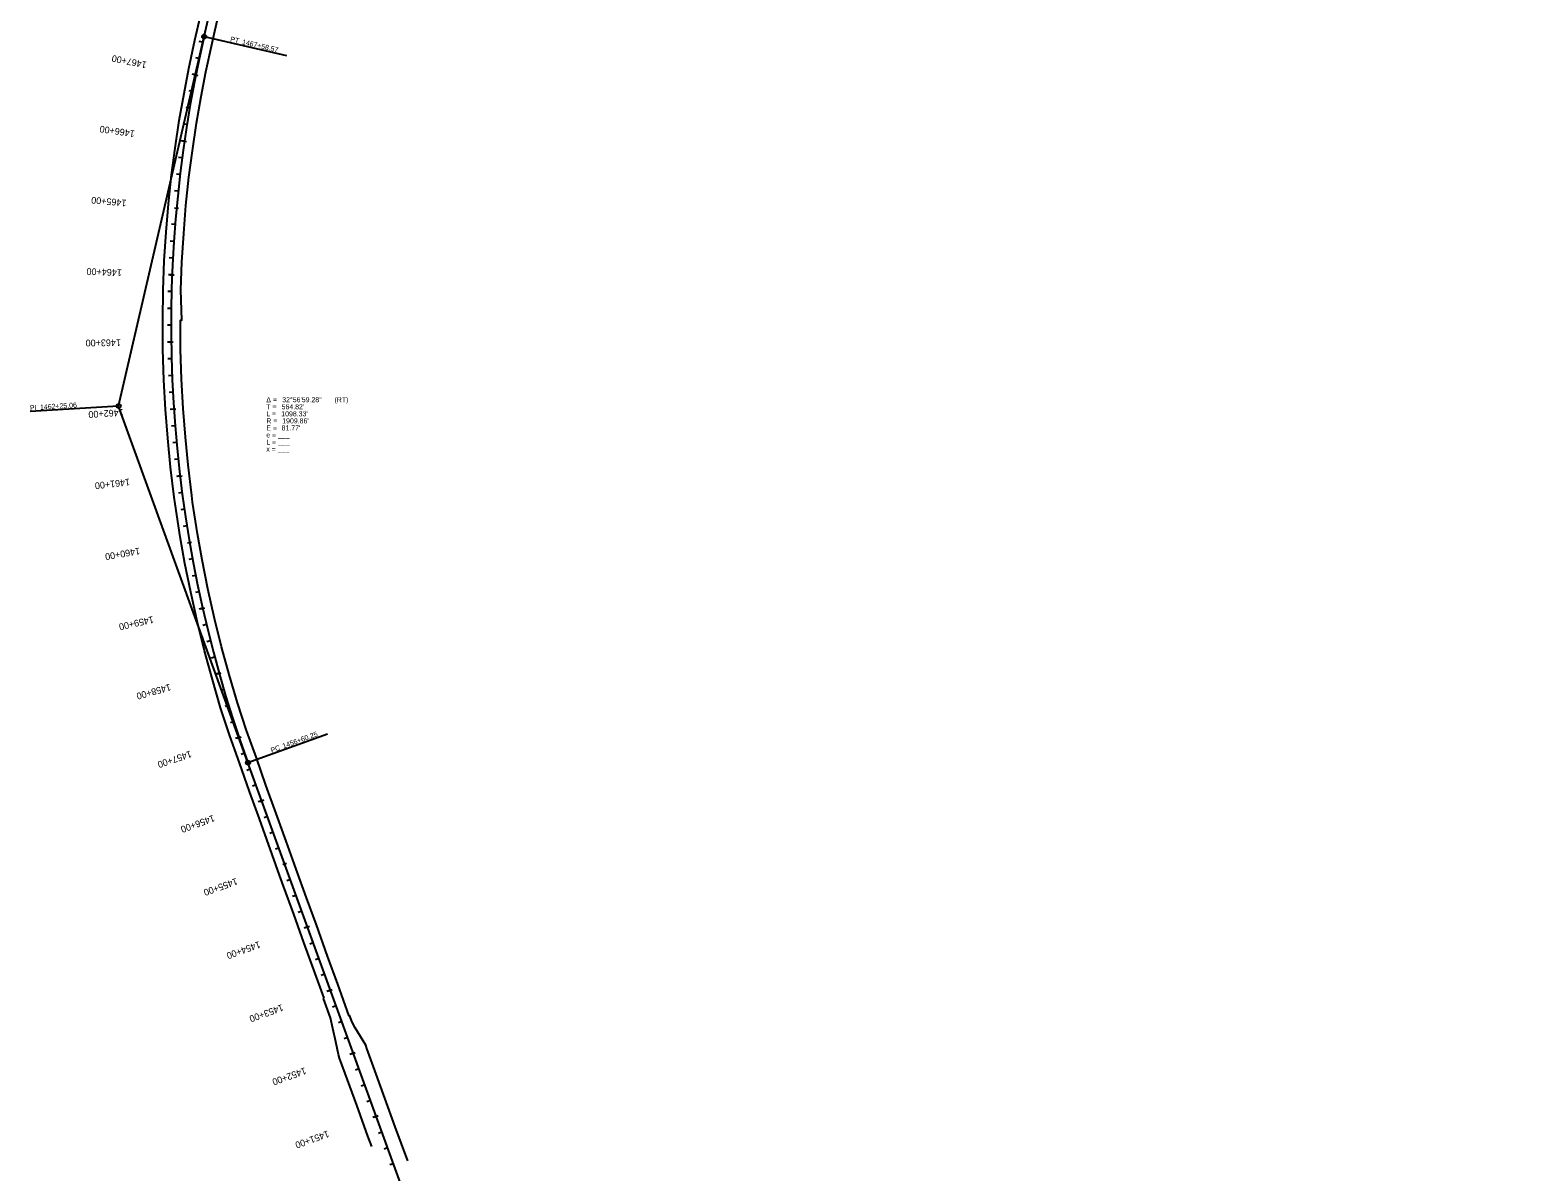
# Model space of a CAD drawing. Extents: x 21596470 to 21601942, y 8263806 to 8275912.
# Drawn here: x 21596470 to 21598714, y 8265512 to 8267212 of the extents above; entities that cross this region are included whole.
import ezdxf

# ---------------------------------------------------------------- set-up
doc = ezdxf.new("R2010")
doc.units = 0
for name, color, linetype in [('DsnShtInsideBorder', 7, 'Continuous'), ('Level 1', 7, 'Continuous'), ('Level 20', 7, 'Continuous'), ('SurTxtLeaderLine', 7, 'Continuous'), ('SurTxtSurveyInformation', 7, 'Continuous'), ('wetNoteSoil', 7, 'Continuous')]:
    doc.layers.add(name, color=color, linetype=linetype)

msp = doc.modelspace()

# ---------------------------------------------------------------- linework, layer by layer
at = {"layer": 'DsnShtInsideBorder'}
for p, q in [((21596728.7, 8267202.6), (21596851.5, 8267174.2)), ((21596851.5, 8267174.2), (21596851.5, 8267174.2)), ((21596601.4, 8266652.3), (21596469.7, 8266644.3)), ((21596469.7, 8266644.3), (21596469.7, 8266644.3)), ((21596793.9, 8266121.3), (21596912.3, 8266164.2)), ((21596912.3, 8266164.2), (21596912.3, 8266164.2))]:
    msp.add_line(p, q, dxfattribs=at)
for centre in [(21596728.7, 8267202.6), (21596601.4, 8266652.3), (21596793.9, 8266121.3)]:
    msp.add_circle(centre, 3.12, dxfattribs=at)
at = {"layer": 'Level 1'}
for p, q in [((21596716.4, 8267145.3), (21596711, 8267146.4)), ((21596699.4, 8267046.8), (21596694, 8267047.5)), ((21596684.6, 8266947.7), (21596690.7, 8266947.2)), ((21596681.1, 8266847.7), (21596675.6, 8266847.9)), ((21596679.7, 8266747.7), (21596674.3, 8266747.6)), ((21596683.6, 8266647.8), (21596678.2, 8266647.4)), ((21596692.7, 8266548.2), (21596687.3, 8266547.6)), ((21596704, 8266448.8), (21596710.1, 8266449.8)), ((21596726.5, 8266351.2), (21596721.2, 8266350)), ((21596751.1, 8266254.3), (21596745.9, 8266252.8)), ((21596780.7, 8266158.8), (21596775.6, 8266157)), ((21596814.4, 8266064.6), (21596809.3, 8266062.8)), ((21596845.6, 8265969.6), (21596851.4, 8265971.7)), ((21596882.6, 8265876.6), (21596877.4, 8265874.7)), ((21596916.6, 8265782.6), (21596911.5, 8265780.7)), ((21596950.7, 8265688.6), (21596945.6, 8265686.7)), ((21596984.8, 8265594.6), (21596979.7, 8265592.7))]:
    msp.add_line(p, q, dxfattribs=at)
at = {"layer": 'Level 20'}
for p, q in [((21596601.4, 8266652.3), (21598714.2, 8275785)), ((21596728.7, 8267202.6), (21598588.8, 8275242.6)), ((21597632.1, 8263808.8), (21596601.4, 8266652.3)), ((21597632.1, 8263808.8), (21596793.9, 8266121.3))]:
    msp.add_line(p, q, dxfattribs=at)
msp.add_arc((21598589.4, 8266772.1), 1909.9, 166.974, 199.9238, dxfattribs=at)
msp.add_arc((21598589.4, 8266772.1), 1909.9, 166.974, 199.9238, dxfattribs=at)
at = {"layer": 'SurTxtLeaderLine'}
for points in [[(21596944.8, 8265743.6), (21596927.5, 8265791.2), (21596912.5, 8265833.3), (21596895.8, 8265879.9), (21596881.2, 8265919.8), (21596865.6, 8265962.8), (21596850.8, 8266004.4), (21596836, 8266045.3), (21596820.7, 8266087.5), (21596806.4, 8266128.4), (21596791.9, 8266169.3), (21596778.2, 8266210.3), (21596765.7, 8266252.3), (21596754.6, 8266293.9), (21596744.2, 8266335.7), (21596734.3, 8266380.1), (21596725.6, 8266423.2), (21596718.8, 8266462.2), (21596711.5, 8266509), (21596710.4, 8266519.1), (21596704.8, 8266564.8), (21596700.9, 8266606.2), (21596697.3, 8266648.6), (21596694.9, 8266692.2), (21596693.7, 8266736.6), (21596693.3, 8266780), (21596695.4, 8266780), (21596694, 8266825.2), (21596695.4, 8266866.8), (21596698.2, 8266909.4), (21596701.5, 8266951.2), (21596705.9, 8266993), (21596711.3, 8267032.5), (21596717.4, 8267073.6), (21596724.2, 8267113.2), (21596731.4, 8267150.2), (21596740.4, 8267192.7), (21596750.3, 8267234.8)], [(21597031.7, 8265528.4), (21597013.3, 8265579), (21596997.9, 8265621.4), (21596983, 8265662.7), (21596971.1, 8265695.8), (21596969.2, 8265700.6), (21596953.4, 8265726.5), (21596948.6, 8265735.7), (21596945.6, 8265744), (21596944.8, 8265743.6)]]:
    msp.add_lwpolyline(points, dxfattribs=at)
at = {"layer": 'SurTxtSurveyInformation'}
for points in [[(21596907.2, 8265770.4), (21596892.1, 8265812.6), (21596877.2, 8265853.6), (21596862.2, 8265895.5), (21596847, 8265937.5), (21596841, 8265953.8), (21596810.9, 8266037.4), (21596796, 8266078.5), (21596781.1, 8266120.8), (21596766.8, 8266161.2), (21596753, 8266202.8), (21596741, 8266245), (21596729, 8266287.8), (21596718.8, 8266329.9), (21596708.7, 8266375.1), (21596700, 8266418), (21596693, 8266457.7), (21596685.3, 8266506.6), (21596684, 8266516.7), (21596678.6, 8266561.4), (21596674.4, 8266604.4), (21596671, 8266647.2), (21596668.6, 8266691.1), (21596667.3, 8266736.8), (21596667.1, 8266780.7), (21596667.8, 8266825.1), (21596669.4, 8266868.6), (21596672, 8266911.2), (21596675.6, 8266953.5), (21596680.1, 8266996.6), (21596685.3, 8267036.2), (21596691.5, 8267077.7), (21596698.7, 8267118), (21596705.8, 8267155.2), (21596715, 8267197.4), (21596724.5, 8267240)], [(21596978.1, 8265549.7), (21596972.5, 8265564.9), (21596955.8, 8265611.1), (21596942.2, 8265648.8), (21596930.4, 8265681.4), (21596928.8, 8265686.4), (21596924.6, 8265705.7), (21596920.3, 8265725.4), (21596916.9, 8265741.1), (21596906.3, 8265770.1), (21596907.2, 8265770.4)]]:
    msp.add_lwpolyline(points, dxfattribs=at)
at = {"layer": 'wetNoteSoil'}
for p, q in [((21596726.8, 8267194.2), (21596721.5, 8267195.4)), ((21596721.4, 8267169.8), (21596716.1, 8267170.9)), ((21596713.4, 8267145.9), (21596719.4, 8267144.7)), ((21596711.7, 8267120.7), (21596706.3, 8267121.7)), ((21596707.3, 8267096.1), (21596701.9, 8267097.1)), ((21596703.2, 8267071.5), (21596697.8, 8267072.3)), ((21596696.4, 8267047.2), (21596702.5, 8267046.3)), ((21596696, 8267022), (21596690.6, 8267022.7)), ((21596692.9, 8266997.2), (21596687.5, 8266997.8)), ((21596690.1, 8266972.3), (21596684.7, 8266972.9)), ((21596684.6, 8266947.7), (21596690.7, 8266947.2)), ((21596685.5, 8266922.6), (21596680.1, 8266923)), ((21596683.7, 8266897.6), (21596678.3, 8266898)), ((21596682.2, 8266872.7), (21596676.8, 8266873)), ((21596678, 8266847.8), (21596684.1, 8266847.6)), ((21596680.2, 8266822.7), (21596674.8, 8266822.9)), ((21596679.7, 8266797.7), (21596674.3, 8266797.8)), ((21596679.6, 8266772.7), (21596674.1, 8266772.7)), ((21596676.7, 8266747.7), (21596682.8, 8266747.8)), ((21596680.2, 8266722.7), (21596674.8, 8266722.6)), ((21596681, 8266697.7), (21596675.6, 8266697.5)), ((21596682.2, 8266672.8), (21596676.7, 8266672.5)), ((21596680.6, 8266647.6), (21596686.7, 8266648)), ((21596685.4, 8266622.9), (21596680, 8266622.4)), ((21596687.5, 8266598), (21596682.1, 8266597.5)), ((21596690, 8266573.1), (21596684.5, 8266572.5)), ((21596689.7, 8266547.9), (21596695.8, 8266548.6)), ((21596695.8, 8266523.4), (21596690.4, 8266522.7)), ((21596699.2, 8266498.7), (21596693.8, 8266497.9)), ((21596703, 8266473.9), (21596697.6, 8266473.1)), ((21596704, 8266448.8), (21596710.1, 8266449.8)), ((21596711.4, 8266424.7), (21596706.1, 8266423.7)), ((21596716.1, 8266400.1), (21596710.8, 8266399)), ((21596721.2, 8266375.6), (21596715.8, 8266374.5)), ((21596723.5, 8266350.5), (21596729.5, 8266351.9)), ((21596732.2, 8266326.9), (21596726.9, 8266325.6)), ((21596738.2, 8266302.6), (21596732.9, 8266301.2)), ((21596744.5, 8266278.4), (21596739.2, 8266277)), ((21596748.2, 8266253.4), (21596754.1, 8266255.1)), ((21596758, 8266230.3), (21596752.8, 8266228.7)), ((21596765.3, 8266206.3), (21596760.1, 8266204.7)), ((21596772.9, 8266182.5), (21596767.7, 8266180.8)), ((21596777.8, 8266157.8), (21596783.6, 8266159.8)), ((21596788.9, 8266135.2), (21596783.8, 8266133.3)), ((21596797.4, 8266111.6), (21596792.2, 8266109.8)), ((21596805.9, 8266088.1), (21596800.8, 8266086.3)), ((21596811.5, 8266063.6), (21596817.3, 8266065.7)), ((21596822.9, 8266041.1), (21596817.8, 8266039.3)), ((21596831.5, 8266017.6), (21596826.3, 8266015.8)), ((21596840, 8265994.1), (21596834.8, 8265992.3)), ((21596845.6, 8265969.6), (21596851.4, 8265971.7)), ((21596857, 8265947.1), (21596851.9, 8265945.2)), ((21596865.5, 8265923.6), (21596860.4, 8265921.7)), ((21596874.1, 8265900.1), (21596868.9, 8265898.2)), ((21596879.7, 8265875.6), (21596885.4, 8265877.6)), ((21596891.1, 8265853.1), (21596886, 8265851.2)), ((21596899.6, 8265829.6), (21596894.5, 8265827.7)), ((21596908.1, 8265806.1), (21596903, 8265804.2)), ((21596913.8, 8265781.5), (21596919.5, 8265783.6)), ((21596925.2, 8265759.1), (21596920, 8265757.2)), ((21596933.7, 8265735.6), (21596928.6, 8265733.7)), ((21596942.2, 8265712.1), (21596937.1, 8265710.2)), ((21596947.8, 8265687.5), (21596953.6, 8265689.6)), ((21596959.2, 8265665.1), (21596954.1, 8265663.2)), ((21596967.8, 8265641.6), (21596962.6, 8265639.7)), ((21596976.3, 8265618.1), (21596971.1, 8265616.2)), ((21596981.9, 8265593.5), (21596987.7, 8265595.6)), ((21596993.3, 8265571), (21596988.2, 8265569.2)), ((21597001.8, 8265547.5), (21596996.7, 8265545.7)), ((21597010.4, 8265524), (21597005.2, 8265522.2))]:
    msp.add_line(p, q, dxfattribs=at)

# ---------------------------------------------------------------- texts
at = {"layer": 'DsnShtInsideBorder'}
for s, rotation, p in [('PT', 346.974, (21596767, 8267195.4)), ('1467+58.57', 346.974, (21596784.6, 8267191.3)), ('PI ', 3.4489, (21596469.6, 8266646)), ('1462+25.06', 3.4489, (21596484.5, 8266646.9)), ('1456+60.25', 19.9238, (21596846.8, 8266142.2)), ('PC', 19.9238, (21596829.3, 8266135.8))]:
    msp.add_text(s, height=7.5, rotation=rotation, dxfattribs=at).set_placement(p)
for s, p in [('T = ', (21596821.2, 8266647.5)), ('Δ = ', (21596821.2, 8266658)), ("564.82'", (21596844, 8266647.5)), ('32°56\'59.28"', (21596844.9, 8266658)), (' (RT)', (21596919.8, 8266658)), ('L = ', (21596821.2, 8266637)), ('R = ', (21596821.2, 8266626.5)), ("1098.33'", (21596843.5, 8266637)), ("1909.86'", (21596844.9, 8266626.5)), ('e = ___ ', (21596821.2, 8266605.5)), ('E = ', (21596821.2, 8266616)), ('L = ___', (21596821.2, 8266595)), ("81.77'", (21596844, 8266616)), ('x = ___', (21596821.2, 8266584.5))]:
    msp.add_text(s, height=7.5, dxfattribs=at).set_placement(p)
at = {"layer": 'Level 1'}
for s, rotation, p in [('1465+00', 174.7312, (21596613.4, 8266959.3)), ('1460+00', 189.7312, (21596632.3, 8266441.5)), ('1455+00', 199.9238, (21596776.3, 8265949.8))]:
    msp.add_text(s, height=10.02, rotation=rotation, dxfattribs=at).set_placement(p)
at = {"layer": 'wetNoteSoil'}
for s, rotation, p in [('1467+00', 168.7312, (21596643.8, 8267164.9)), ('1466+00', 171.7312, (21596625.9, 8267062.5)), ('1465+00', 174.7312, (21596613.4, 8266959.3)), ('1464+00', 177.7312, (21596606.3, 8266855.7)), ('1463+00', 180.7312, (21596604.7, 8266751.8)), ('1462+00', 183.7312, (21596608.5, 8266647.9)), ('1461+00', 186.7312, (21596617.7, 8266544.4)), ('1460+00', 189.7312, (21596632.3, 8266441.5)), ('1459+00', 192.7312, (21596652.3, 8266339.6)), ('1458+00', 195.7312, (21596677.6, 8266238.8)), ('1457+00', 198.7312, (21596708.1, 8266139.4)), ('1456+00', 199.9238, (21596742.2, 8266043.8)), ('1455+00', 199.9238, (21596776.3, 8265949.8)), ('1454+00', 199.9238, (21596810.4, 8265855.7)), ('1453+00', 199.9238, (21596844.4, 8265761.7)), ('1452+00', 199.9238, (21596878.5, 8265667.7)), ('1451+00', 199.9238, (21596912.6, 8265573.7))]:
    msp.add_text(s, height=10.02, rotation=rotation, dxfattribs=at).set_placement(p)

doc.saveas('drawing.dxf')
